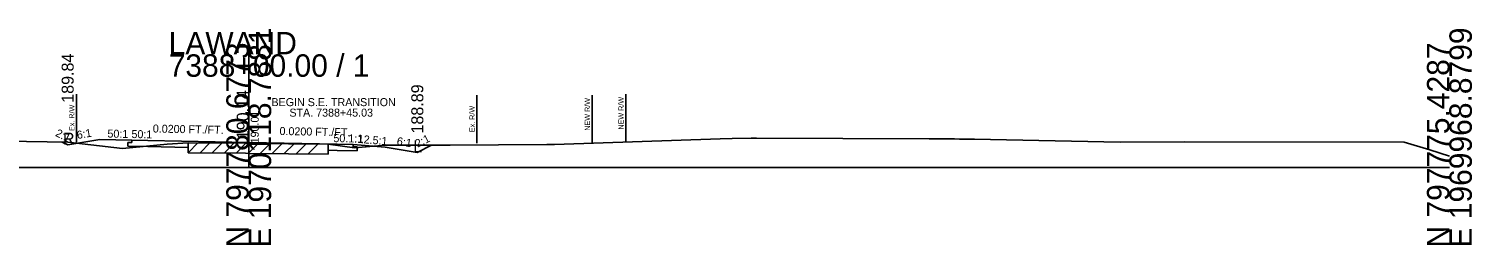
# Model space of a CAD drawing. Extents: x -26 to 303, y -10 to 1532.
# Drawn here: x 122.5 to 302.8, y 490.3 to 517.3 of the extents above; entities that cross this region are included whole.
import ezdxf

# ---------------------------------------------------------------- set-up
doc = ezdxf.new("R2010")
doc.units = 0
for name, color, linetype in [('RD_GPK_XS_Cell', 7, 'Continuous'), ('RD_XS_Base', 7, 'Continuous'), ('RD_XS_EarthShd', 7, 'Continuous'), ('RD_XS_ExGround', 7, 'Continuous'), ('RD_XS_ExPaveRet', 7, 'Continuous'), ('RD_XS_ExRW', 7, 'Continuous'), ('RD_XS_Misc_Line', 7, 'Continuous'), ('RD_XS_NewRW', 7, 'Continuous'), ('RD_XS_Pave', 7, 'Continuous'), ('RD_XS_PaveOvlay', 7, 'Continuous'), ('RD_XS_PaveShd', 7, 'Continuous'), ('RD_XS_TieSlope', 7, 'Continuous'), ('RD_XS_TX_Elev_EX', 7, 'Continuous'), ('RD_XS_TX_Elev_PR', 7, 'Continuous'), ('RD_XS_TX_Misc', 7, 'Continuous'), ('RD_XS_TX_MkPT', 7, 'Continuous'), ('RD_XS_TX_Notes', 7, 'Continuous'), ('RD_XS_TX_Profile', 7, 'Continuous'), ('RD_XS_TX_ShdSlope', 7, 'Continuous'), ('RD_XS_TX_Slope', 7, 'Continuous')]:
    doc.layers.add(name, color=color, linetype=linetype)

msp = doc.modelspace()

# ---------------------------------------------------------------- linework, layer by layer
at = {"layer": 'RD_GPK_XS_Cell'}
for p, q in [((150, 500), (150, 514.13)), ((0, 500), (150, 500)), ((150, 500), (300, 500))]:
    msp.add_line(p, q, dxfattribs=at)
at = {"layer": 'RD_XS_Base'}
for p, q in [((134.89, 503.14), (135.39, 503.13)), ((134.89, 502.66), (134.89, 503.14)), ((135.39, 503.13), (135.39, 503.43)), ((137.39, 502.61), (134.89, 502.66)), ((137.39, 502.61), (142.42, 502.51)), ((159.93, 502.16), (161.05, 502.13)), ((161.05, 502.13), (163.55, 502.08)), ((163.05, 502.57), (163.05, 502.87)), ((163.55, 502.56), (163.05, 502.57)), ((163.55, 502.08), (163.55, 502.56))]:
    msp.add_line(p, q, dxfattribs=at)
at = {"layer": 'RD_XS_EarthShd'}
for p, q in [((135.39, 503.43), (131.39, 503.51)), ((163.05, 502.87), (167.05, 502.55))]:
    msp.add_line(p, q, dxfattribs=at)
at = {"layer": 'RD_XS_ExGround'}
msp.add_lwpolyline([(78.47, 503.94), (127.41, 503.16), (134.24, 502.38), (139.8, 502.9), (142.42, 503.09), (149.6, 503.02), (150, 503.01), (159.93, 502.93), (163.21, 502.44), (167.09, 502.79), (175.16, 502.77), (187.25, 502.87), (188.19, 502.87), (208.91, 503.57), (210.41, 503.62), (212.78, 503.68), (213.42, 503.68), (235.02, 503.56), (238.16, 503.56), (238.8, 503.54), (240.69, 503.53), (244.66, 503.46), (258.85, 503.17), (266.89, 503.22), (294.36, 503.15), (297.55, 502.21), (300, 501.43)], dxfattribs=at)
at = {"layer": 'RD_XS_ExPaveRet'}
for p, q in [((142.42, 501.84), (142.42, 503.09)), ((142.42, 501.84), (149.6, 501.77)), ((149.6, 501.77), (150, 501.76)), ((150, 501.76), (159.93, 501.68)), ((159.93, 502.93), (159.93, 501.68))]:
    msp.add_line(p, q, dxfattribs=at)
at = {"layer": 'RD_XS_ExRW'}
for p, q in [((128.48, 509.17), (128.48, 503.17)), ((178.48, 509.03), (178.48, 503.03))]:
    msp.add_line(p, q, dxfattribs=at)
at = {"layer": 'RD_XS_Misc_Line'}
for p, q in [((142.42, 501.84), (143.65, 503.08)), ((143.92, 501.83), (145.15, 503.06)), ((145.42, 501.81), (146.65, 503.05)), ((146.92, 501.8), (148.15, 503.03)), ((148.42, 501.78), (149.65, 503.02)), ((149.92, 501.76), (151.16, 503)), ((151.42, 501.75), (152.66, 502.99)), ((152.92, 501.74), (154.16, 502.98)), ((154.42, 501.73), (155.66, 502.97)), ((155.92, 501.71), (157.16, 502.95)), ((157.42, 501.7), (158.66, 502.94))]:
    msp.add_line(p, q, dxfattribs=at)
at = {"layer": 'RD_XS_NewRW'}
for p, q in [((192.9, 509.03), (192.9, 503.03)), ((197.11, 509.17), (197.11, 503.17))]:
    msp.add_line(p, q, dxfattribs=at)
at = {"layer": 'RD_XS_Pave'}
for p, q in [((137.39, 503.39), (150, 503.13)), ((150, 503.13), (161.05, 502.91))]:
    msp.add_line(p, q, dxfattribs=at)
at = {"layer": 'RD_XS_PaveOvlay'}
for p, q in [((142.42, 503.09), (149.6, 503.02)), ((142.42, 503.09), (142.42, 502.57)), ((149.6, 503.02), (150, 503.01)), ((150, 503.01), (159.93, 502.93)), ((159.93, 502.93), (159.93, 502.22))]:
    msp.add_line(p, q, dxfattribs=at)
at = {"layer": 'RD_XS_PaveShd'}
for p, q in [((137.39, 503.39), (135.39, 503.43)), ((161.05, 502.91), (163.05, 502.87))]:
    msp.add_line(p, q, dxfattribs=at)
at = {"layer": 'RD_XS_TieSlope'}
for p, q in [((127.38, 502.84), (126.71, 503.17)), ((131.39, 503.51), (127.38, 502.84)), ((167.05, 502.55), (171.06, 501.89)), ((171.06, 501.89), (172.84, 502.78))]:
    msp.add_line(p, q, dxfattribs=at)

# ---------------------------------------------------------------- texts
at = {"layer": 'RD_GPK_XS_Cell'}
for s, p in [('LAWAND', (140, 514.13)), ('7388+00.00 / 1', (140, 511.33))]:
    msp.add_text(s, height=2.8, dxfattribs=at).set_placement(p)
for s, p in [('E 1970118.7881', (152.8, 490)), ('E 1969968.8799', (302.8, 490)), ('N 797780.6773', (150, 490)), ('N 797775.4287', (300, 490))]:
    msp.add_text(s, height=2.8, rotation=90, dxfattribs=at).set_placement(p)
at = {"layer": 'RD_XS_ExRW'}
for p in [(128.23, 504.55), (178.23, 504.41)]:
    msp.add_text('Ex. R/W ', height=0.65, rotation=90, dxfattribs=at).set_placement(p)
at = {"layer": 'RD_XS_NewRW'}
for p in [(192.63, 504.59), (196.84, 504.73)]:
    msp.add_text('NEW R/W ', height=0.65, rotation=90, dxfattribs=at).set_placement(p)
at = {"layer": 'RD_XS_TX_Elev_EX'}
msp.add_text('190.01', height=1, rotation=90, dxfattribs=at).set_placement((151.25, 503.01))
at = {"layer": 'RD_XS_TX_Elev_PR'}
msp.add_text('190.14', height=1.5, rotation=90, dxfattribs=at).set_placement((150, 503.53))
at = {"layer": 'RD_XS_TX_Misc'}
for s, p in [('189.84', (128.13, 508.08)), ('188.89', (171.81, 504.24))]:
    msp.add_text(s, height=1.5, rotation=90, dxfattribs=at).set_placement(p)
at = {"layer": 'RD_XS_TX_MkPT'}
for s, p in [('R', (126.79, 502.84)), ('L', (170.55, 501.89))]:
    msp.add_text(s, height=1.5, dxfattribs=at).set_placement(p)
at = {"layer": 'RD_XS_TX_Notes'}
for s, p in [('BEGIN S.E. TRANSITION', (152.84, 507.66)), ('STA. 7388+45.03', (155.08, 506.35))]:
    msp.add_text(s, height=1, dxfattribs=at).set_placement(p)
at = {"layer": 'RD_XS_TX_Profile'}
for s, rotation, p in [('50:1', 358.855, (135.34, 503.68)), ('50.1:1', 358.8556, (160.57, 503.17))]:
    msp.add_text(s, height=1, rotation=rotation, dxfattribs=at).set_placement(p)
at = {"layer": 'RD_XS_TX_ShdSlope'}
for s, rotation, p in [('50:1', 358.855, (132.34, 503.74)), ('12.5:1', 355.4314, (163.59, 503.08))]:
    msp.add_text(s, height=1, rotation=rotation, dxfattribs=at).set_placement(p)
at = {"layer": 'RD_XS_TX_Slope'}
for s, rotation, p in [('0.0200 FT./FT.', 358.855, (138.01, 504.37)), ('0.0200 FT./FT.', 358.8556, (153.84, 504.06)), ('2:1', 333.4496, (125.76, 503.97)), ('6:1', 9.4564, (128.6, 503.55)), ('6:1', 350.5485, (168.44, 502.83)), ('2:1', 26.5383, (171.09, 502.46))]:
    msp.add_text(s, height=1, rotation=rotation, dxfattribs=at).set_placement(p)

doc.saveas('drawing.dxf')
